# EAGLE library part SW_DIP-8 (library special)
DIP SWITCH
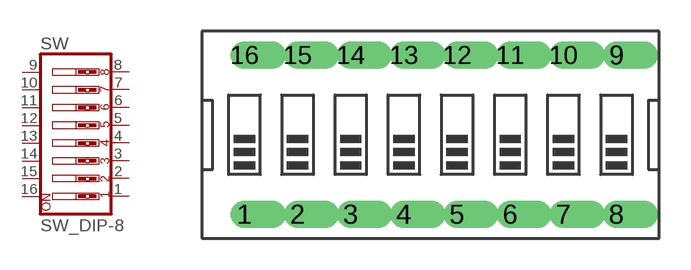
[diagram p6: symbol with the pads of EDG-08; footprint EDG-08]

Designator prefix SW

## SW_DIP-8  [EDG-08]
1  1  pas
2  2  pas
3  3  pas
4  4  pas
5  5  pas
6  6  pas
7  7  pas
8  8  pas
9  9  pas
10  10  pas
11  11  pas
12  12  pas
13  13  pas
14  14  pas
15  15  pas
16  16  pas

## Footprint EDG-08 (pad centres in mm)
DIP SWITCH
drill 0.813 offset: 1 -8.89,-3.81; 2 -6.35,-3.81; 3 -3.81,-3.81; 4 -1.27,-3.81; 5 1.27,-3.81; 6 3.81,-3.81; 7 6.35,-3.81; 8 8.89,-3.81; 9 8.89,3.81; 10 6.35,3.81; 11 3.81,3.81; 12 1.27,3.81; 13 -1.27,3.81; 14 -3.81,3.81; 15 -6.35,3.81; 16 -8.89,3.81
